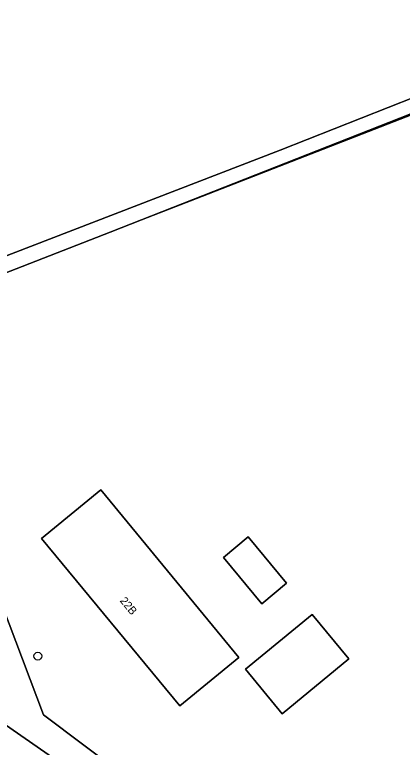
# Model space of a CAD drawing. Extents: x 163859 to 164644, y 379566 to 382155.
# Drawn here: x 164456.9 to 164505.3, y 381680.8 to 381772.4 of the extents above; entities that cross this region are included whole.
import ezdxf

# ---------------------------------------------------------------- set-up
doc = ezdxf.new("R2010")
doc.units = 0
for name, color, linetype in [('IMGEO_Boom', 7, 'Continuous'), ('IMGEO_Erf', 7, 'Continuous'), ('IMGEO_Grasland_agrarisch', 7, 'Continuous'), ('IMGEO_Groenvoorziening', 7, 'Continuous'), ('IMGEO_Hek', 7, 'Continuous'), ('IMGEO_Pand', 7, 'Continuous'), ('IMGEO_Pand_nummerreeks', 7, 'Continuous'), ('IMGEO_Rijbaan_lokaal_gesloten', 7, 'Continuous')]:
    doc.layers.add(name, color=color, linetype=linetype)

msp = doc.modelspace()

# ---------------------------------------------------------------- linework, layer by layer
at = {"layer": 'IMGEO_Boom'}
msp.add_circle((164459.807, 381692.21), 0.489, dxfattribs=at)
at = {"layer": 'IMGEO_Erf'}
for points in [[(164600.098, 381839.014), (164585.232, 381833.12), (164548.829, 381818.751), (164518.638, 381806.884), (164490.643, 381796.474), (164469.448, 381788.316), (164427.546, 381772.442), (164433.526, 381754.803), (164433.997, 381752.734), (164434.331, 381751.745), (164440.833, 381734.263), (164457.1, 381740.602), (164468.83, 381745.172), (164534.647, 381771.115), (164538.087, 381770.586), (164545.187, 381772.796), (164541.615, 381789.068), (164575.754, 381802.969), (164581.346, 381805.246), (164580.013, 381810.414), (164568.257, 381805.885), (164561.666, 381820.235), (164600.165, 381835.553), (164600.153, 381836.164)], [(164443.539, 381737.474), (164442.939, 381737.247), (164436.966, 381753.014), (164430.965, 381770.512), (164456.78, 381779.759), (164478.348, 381787.868), (164505.546, 381798.321), (164526.662, 381806.514), (164530.385, 381805.09), (164531.541, 381804.475), (164532.487, 381803.404), (164538.297, 381784.937), (164539.439, 381780.675), (164539.19, 381777.888), (164537.822, 381775.597), (164535.89, 381774.091), (164533.834, 381772.761), (164490.018, 381755.433)], [(164477.518, 381685.988), (164460.279, 381706.916), (164467.652, 381712.978), (164484.868, 381692.033)], [(164490.829, 381701.31), (164487.743, 381698.765), (164482.971, 381704.551), (164486.057, 381707.096)], [(164498.588, 381691.859), (164490.287, 381685.013), (164485.71, 381690.563), (164494.011, 381697.409)]]:
    msp.add_lwpolyline(points, close=True, dxfattribs=at)
msp.add_lwpolyline([(164545.187, 381772.796), (164538.087, 381770.586), (164534.647, 381771.115), (164468.83, 381745.172), (164457.1, 381740.602), (164440.833, 381734.263), (164442.117, 381733.052), (164446.861, 381722.173), (164449.308, 381717.487), (164452.858, 381710.476), (164454.684, 381705.828), (164452.839, 381705.104), (164456.242, 381696.233), (164460.508, 381684.892), (164470.413, 381677.426)], dxfattribs=at)
at = {"layer": 'IMGEO_Grasland_agrarisch'}
msp.add_lwpolyline([(164443.539, 381737.474), (164490.018, 381755.433), (164533.834, 381772.761), (164535.89, 381774.091), (164537.822, 381775.597), (164539.19, 381777.888), (164539.439, 381780.675), (164538.297, 381784.937), (164532.487, 381803.404), (164531.541, 381804.475), (164530.385, 381805.09), (164526.662, 381806.514), (164505.546, 381798.321), (164478.348, 381787.868), (164456.78, 381779.759), (164430.965, 381770.512), (164436.966, 381753.014), (164442.939, 381737.247)], close=True, dxfattribs=at)
at = {"layer": 'IMGEO_Groenvoorziening'}
msp.add_lwpolyline([(164455.903, 381683.819), (164455.774, 381683.629), (164466.526, 381676.141), (164470.413, 381677.426), (164460.508, 381684.892), (164456.242, 381696.233), (164452.839, 381705.104), (164451.098, 381709.418), (164447.311, 381716.527), (164449.308, 381717.487), (164446.861, 381722.173), (164445.218, 381721.442), (164440.48, 381732.584), (164442.117, 381733.052), (164440.833, 381734.263), (164434.331, 381751.745), (164433.997, 381752.734), (164433.526, 381754.803), (164427.546, 381772.442), (164427.349, 381773.022), (164418.253, 381799.855)], dxfattribs=at)
at = {"layer": 'IMGEO_Hek'}
for points in [[(164512.128, 381762.042), (164479.577, 381749.36)], [(164479.577, 381749.36), (164468.83, 381745.172)], [(164468.83, 381745.172), (164457.1, 381740.602)], [(164457.1, 381740.602), (164440.833, 381734.263)]]:
    msp.add_lwpolyline(points, dxfattribs=at)
at = {"layer": 'IMGEO_Pand'}
for points in [[(164477.518, 381685.988), (164484.868, 381692.033), (164467.652, 381712.978), (164460.279, 381706.916)], [(164490.829, 381701.31), (164486.057, 381707.096), (164482.971, 381704.551), (164487.743, 381698.765)], [(164490.287, 381685.013), (164498.588, 381691.859), (164494.011, 381697.409), (164485.71, 381690.563)]]:
    msp.add_lwpolyline(points, close=True, dxfattribs=at)
at = {"layer": 'IMGEO_Rijbaan_lokaal_gesloten'}
msp.add_lwpolyline([(164503.048, 381650.429), (164500, 381652.587), (164485.583, 381662.794), (164479.098, 381667.385), (164474.908, 381670.303), (164466.526, 381676.141), (164455.774, 381683.629), (164441.191, 381693.787), (164424.684, 381705.234)], dxfattribs=at)

# ---------------------------------------------------------------- texts
at = {"layer": 'IMGEO_Pand_nummerreeks'}
msp.add_text('22B', height=1, rotation=309.47789, dxfattribs=at).set_placement((164469.982, 381699.101))

doc.saveas('drawing.dxf')
